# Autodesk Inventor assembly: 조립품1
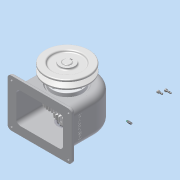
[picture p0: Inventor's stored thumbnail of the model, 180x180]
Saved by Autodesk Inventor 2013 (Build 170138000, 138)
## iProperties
Created: 2016-01
Part Number: 조립품1
Document SubType Name: Assembly
Designer: Administrator
Author: Administrator
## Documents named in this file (16)
- C:\Users\Administrator\Desktop\460106V1036\조립품1.iam
- C:\Users\Administrator\Desktop\460106V1036\답안도면.ipt
- C:\Users\Administrator\Desktop\460106V1036\뒤커버.ipt
- C:\Users\Administrator\Desktop\460106V1036\멈춤나사 - M4x10.ipt
- C:\Users\Administrator\Desktop\460106V1036\베어링 6203.ipt
- C:\Users\Administrator\Desktop\460106V1036\볼트 M3 x 8.ipt
- C:\Users\Administrator\Desktop\460106V1036\볼트 M3 x 10.ipt
- C:\Users\Administrator\Desktop\460106V1036\부시1.ipt
- C:\Users\Administrator\Desktop\460106V1036\부시2.ipt
- C:\Users\Administrator\Desktop\460106V1036\스퍼기어.ipt
- C:\Users\Administrator\Desktop\460106V1036\앞커버.ipt
- C:\Users\Administrator\Desktop\460106V1036\오일씰 28 40 8.ipt
- C:\Users\Administrator\Desktop\460106V1036\축.ipt
- C:\Users\Administrator\Desktop\460106V1036\키 - 5 x 5 x 18.ipt
- C:\Users\Administrator\Desktop\460106V1036\키 - 6 x 6 x 22.ipt
- C:\Users\Administrator\Desktop\460106V1036\V-벨트풀리.ipt
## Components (3 placed, 3 different names)
1. ISO 4762 M3 x 8:1
2. ISO 4762 M3 x 10:1
3. V-벨트풀리:1
